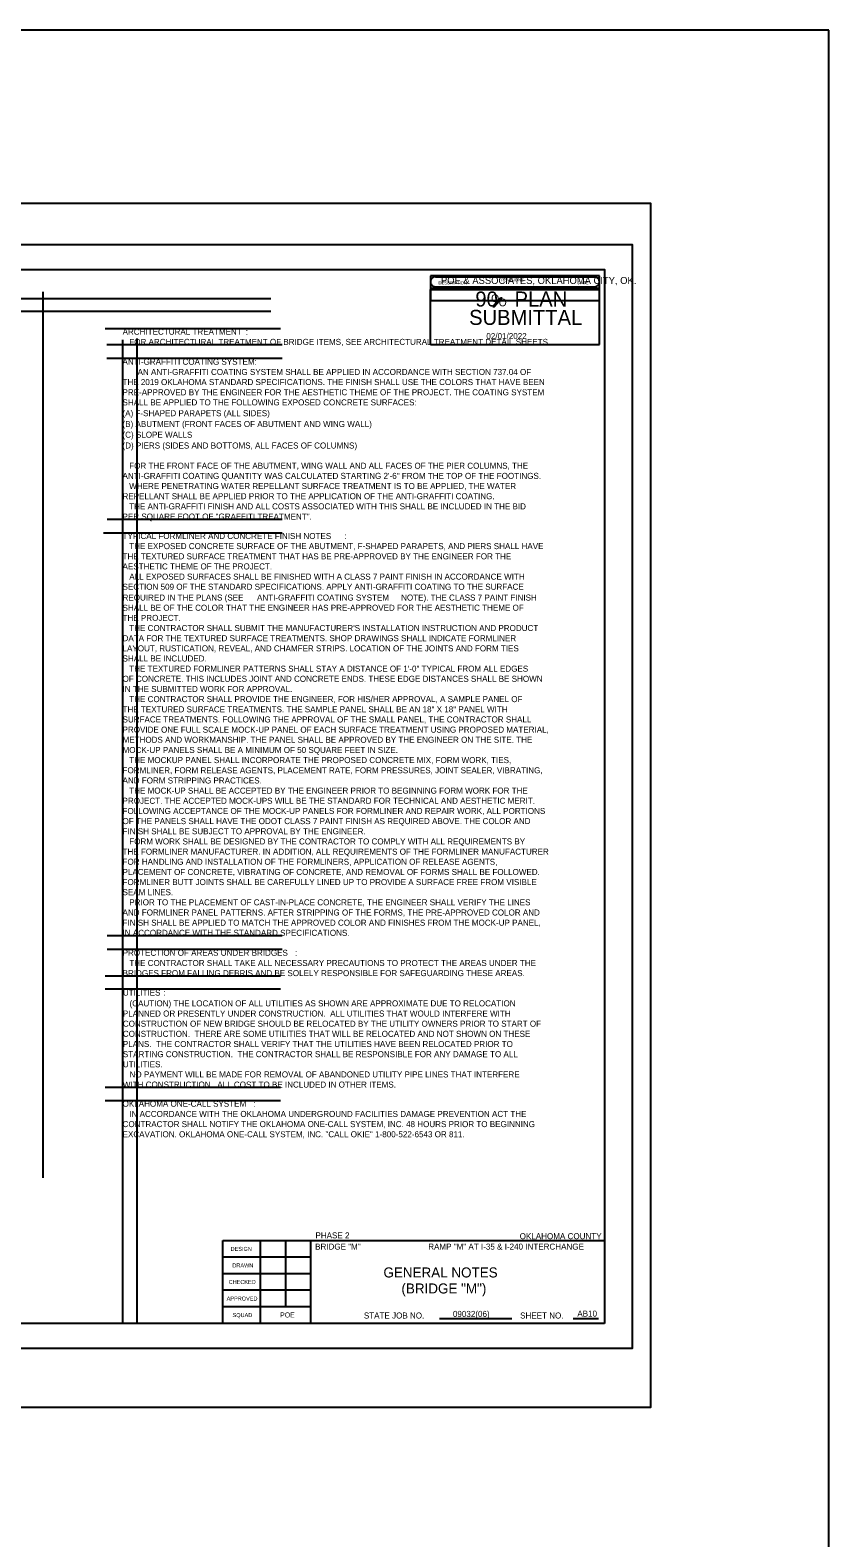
# Model space of a CAD drawing. Extents: x 12303.1 to 12355.9, y 579 to 640.5.
# Drawn here: x 12340.01 to 12355.91, y 610.44 to 640.49 of the extents above; entities that cross this region are included whole.
import ezdxf

# ---------------------------------------------------------------- set-up
doc = ezdxf.new("R2010")
doc.units = 0
for name, color, linetype in [('S', 7, 'Continuous'), ('SHT_Plot_Shape_Full', 7, 'Continuous'), ('SHT_Plot_Shape_Half', 7, 'Continuous'), ('SHT_Sheet_Border', 7, 'Continuous'), ('SHT_Stamp_90_Submit', 7, 'Continuous'), ('SHT_Stamp_Rev_Block', 7, 'Continuous'), ('SHT_Standard_Sheet_Lines', 7, 'Continuous'), ('SHT_Standard_Sheet_Txt', 7, 'Continuous'), ('T', 7, 'Continuous'), ('T-Title', 7, 'Continuous')]:
    doc.layers.add(name, color=color, linetype=linetype)

msp = doc.modelspace()

# ---------------------------------------------------------------- linework, layer by layer
at = {"layer": 'Defpoints'}
for p, q in [((12340.263, 635.276), (12340.263, 617.62)), ((12319.948, 635.141), (12344.799, 635.141)), ((12319.948, 634.891), (12344.799, 634.891)), ((12344.991, 634.538), (12341.502, 634.538)), ((12341.85, 634.316), (12341.85, 614.717)), ((12342.134, 634.344), (12342.134, 614.717)), ((12345.028, 634.215), (12341.539, 634.215)), ((12345.028, 633.945), (12341.539, 633.945)), ((12345.03, 630.735), (12341.54, 630.735)), ((12344.96, 630.466), (12341.471, 630.466)), ((12345.03, 630.466), (12341.54, 630.466)), ((12345.03, 622.44), (12341.54, 622.44)), ((12345.03, 622.17), (12341.54, 622.17)), ((12344.991, 621.637), (12341.502, 621.637)), ((12344.991, 621.375), (12341.502, 621.375)), ((12344.991, 619.416), (12341.502, 619.416)), ((12344.991, 619.154), (12341.502, 619.154))]:
    msp.add_line(p, q, dxfattribs=at)
at = {"layer": 'S'}
msp.add_lwpolyline([(12355.912, 640.488), (12312.476, 640.488), (12312.476, 579.031), (12355.912, 579.031)], close=True, dxfattribs=at)
at = {"layer": 'SHT_Plot_Shape_Full'}
msp.add_lwpolyline([(12316.36, 637.042), (12352.36, 637.042), (12352.36, 613.042), (12316.36, 613.042)], close=True, dxfattribs=at)
at = {"layer": 'SHT_Plot_Shape_Half'}
msp.add_lwpolyline([(12317.998, 636.217), (12351.998, 636.217), (12351.998, 614.217), (12317.998, 614.217)], close=True, dxfattribs=at)
at = {"layer": 'SHT_Sheet_Border'}
for p, q in [((12343.848, 614.717), (12343.848, 616.367)), ((12343.848, 616.367), (12351.448, 616.367)), ((12345.598, 614.717), (12345.598, 616.368))]:
    msp.add_line(p, q, dxfattribs=at)
msp.add_lwpolyline([(12351.448, 614.717), (12319.948, 614.717), (12319.948, 635.717), (12351.448, 635.717)], close=True, dxfattribs=at)
at = {"layer": 'SHT_Stamp_90_Submit'}
for p, q in [((12348.079, 635.572), (12351.245, 635.572)), ((12347.979, 635.322), (12351.345, 635.322)), ((12347.979, 634.223), (12347.979, 635.322)), ((12348.079, 635.372), (12351.245, 635.372)), ((12349.222, 634.984), (12349.377, 635.157)), ((12349.24, 634.984), (12349.395, 635.157)), ((12349.245, 634.984), (12349.4, 635.157)), ((12349.252, 634.984), (12349.408, 635.157)), ((12349.377, 635.157), (12349.408, 635.157)), ((12351.345, 634.223), (12351.345, 635.322)), ((12349.222, 634.984), (12349.252, 634.984)), ((12347.979, 634.223), (12351.345, 634.223))]:
    msp.add_line(p, q, dxfattribs=at)
for centre, start, end in [((12348.079, 635.473), 89.9952, 270), ((12351.245, 635.473), 270, 90.0048)]:
    msp.add_arc(centre, 0.1, start, end, dxfattribs=at)
at = {"layer": 'SHT_Stamp_Rev_Block'}
for p, q in [((12347.979, 635.593), (12347.979, 635.093)), ((12351.345, 635.593), (12347.979, 635.593)), ((12351.345, 635.093), (12351.345, 635.593)), ((12351.345, 635.343), (12347.979, 635.343)), ((12351.345, 635.093), (12347.979, 635.093))]:
    msp.add_line(p, q, dxfattribs=at)
at = {"layer": 'SHT_Standard_Sheet_Lines'}
for p, q in [((12344.598, 614.717), (12344.598, 616.368)), ((12345.098, 615.048), (12345.098, 616.368)), ((12348.159, 614.814), (12349.599, 614.814)), ((12350.823, 614.814), (12351.326, 614.814))]:
    msp.add_line(p, q, dxfattribs=at)
for points in [[(12345.598, 616.037), (12343.848, 616.037)], [(12345.598, 615.707), (12343.848, 615.707)], [(12345.598, 615.377), (12343.848, 615.377)], [(12345.598, 615.047), (12343.848, 615.047)]]:
    msp.add_lwpolyline(points, dxfattribs=at)

# ---------------------------------------------------------------- texts
at = {"layer": 'SHT_Stamp_90_Submit'}
for s, height, p in [('POE & ASSOCIATES, OKLAHOMA CITY, OK.', 0.14, (12348.189, 635.43)), ('90   PLAN', 0.3, (12348.874, 634.98)), ('O', 0.153, (12349.187, 635.069)), ('SUBMITTAL', 0.3, (12348.75, 634.614)), ('O', 0.153, (12349.339, 634.985)), ('02/01/2022', 0.12, (12349.093, 634.332))]:
    msp.add_text(s, height=height, rotation=360, dxfattribs=at).set_placement(p)
at = {"layer": 'SHT_Stamp_Rev_Block'}
for s, p in [('DESCRIPTION', (12348.139, 635.422)), ('REVISIONS', (12349.388, 635.481)), ('DATE', (12350.908, 635.426))]:
    msp.add_text(s, height=0.06, dxfattribs=at).set_placement(p)
at = {"layer": 'SHT_Standard_Sheet_Txt'}
for s, height, p in [('DESIGN', 0.08, (12344, 616.162)), ('DRAWN', 0.08, (12344.035, 615.832)), ('CHECKED', 0.08, (12343.961, 615.502)), ('APPROVED', 0.08, (12343.922, 615.172)), ('SQUAD', 0.08, (12344.039, 614.842)), ('STATE JOB NO.', 0.12, (12346.654, 614.814)), ('SHEET NO. ', 0.12, (12349.765, 614.814))]:
    msp.add_text(s, height=height, dxfattribs=at).set_placement(p)
at = {"layer": 'T'}
for s, height, p in [('ARCHITECTURAL TREATMENT', 0.12, (12341.85, 634.418)), ('   FOR ARCHITECTURAL TREATMENT OF BRIDGE ITEMS, SEE ARCHITECTURAL TREATMENT DETAIL SHEETS.', 0.12, (12341.85, 634.216)), (':', 0.12, (12344.302, 634.418)), ('ANTI-GRAFFITI COATING SYSTEM:', 0.12, (12341.848, 633.82)), ('AN ANTI-GRAFFITI COATING SYSTEM SHALL BE APPLIED IN ACCORDANCE WITH SECTION 737.04 OF ', 0.12, (12342.148, 633.617)), ('THE 2019 OKLAHOMA STANDARD SPECIFICATIONS. THE FINISH SHALL USE THE COLORS THAT HAVE BEEN ', 0.12, (12341.848, 633.415)), ('SHALL BE APPLIED TO THE FOLLOWING EXPOSED CONCRETE SURFACES:', 0.12, (12341.848, 633.01)), ('PRE-APPROVED BY THE ENGINEER FOR THE AESTHETIC THEME OF THE PROJECT. THE COATING SYSTEM ', 0.12, (12341.848, 633.212)), ('(A) F-SHAPED PARAPETS (ALL SIDES)', 0.12, (12341.848, 632.795)), ('(B) ABUTMENT (FRONT FACES OF ABUTMENT AND WING WALL)', 0.12, (12341.848, 632.58)), ('(C) SLOPE WALLS', 0.12, (12341.848, 632.366)), ('(D) PIERS (SIDES AND BOTTOMS, ALL FACES OF COLUMNS)', 0.12, (12341.848, 632.151)), ('   FOR THE FRONT FACE OF THE ABUTMENT, WING WALL AND ALL FACES OF THE PIER COLUMNS, THE ', 0.12, (12341.848, 631.748)), ('ANTI-GRAFFITI COATING QUANTITY WAS CALCULATED STARTING 2\'-6" FROM THE TOP OF THE FOOTINGS.', 0.12, (12341.848, 631.546)), ('REPELLANT SHALL BE APPLIED PRIOR TO THE APPLICATION OF THE ANTI-GRAFFITI COATING.', 0.12, (12341.848, 631.141)), ('   WHERE PENETRATING WATER REPELLANT SURFACE TREATMENT IS TO BE APPLIED, THE WATER ', 0.12, (12341.848, 631.343)), ('   THE ANTI-GRAFFITI FINISH AND ALL COSTS ASSOCIATED WITH THIS SHALL BE INCLUDED IN THE BID ', 0.12, (12341.848, 630.938)), ('PER SQUARE FOOT OF "GRAFFITI TREATMENT".', 0.12, (12341.848, 630.735)), ('TYPICAL FORMLINER AND CONCRETE FINISH NOTES', 0.12, (12341.849, 630.348)), (':', 0.12, (12346.267, 630.348)), ('THE TEXTURED SURFACE TREATMENT THAT HAS BE PRE-APPROVED BY THE ENGINEER FOR THE ', 0.12, (12341.849, 629.943)), ('   THE EXPOSED CONCRETE SURFACE OF THE ABUTMENT, F-SHAPED PARAPETS, AND PIERS SHALL HAVE ', 0.12, (12341.849, 630.146)), ('AESTHETIC THEME OF THE PROJECT.', 0.12, (12341.849, 629.741)), ('SECTION 509 OF THE STANDARD SPECIFICATIONS. APPLY ANTI-GRAFFITI COATING TO THE SURFACE ', 0.12, (12341.849, 629.336)), ('   ALL EXPOSED SURFACES SHALL BE FINISHED WITH A CLASS 7 PAINT FINISH IN ACCORDANCE WITH ', 0.12, (12341.849, 629.538)), ('REQUIRED IN THE PLANS (SEE ', 0.12, (12341.849, 629.121)), ('ANTI-GRAFFITI COATING SYSTEM', 0.12, (12344.526, 629.121)), (' NOTE). THE CLASS 7 PAINT FINISH ', 0.12, (12347.351, 629.121)), ('THE PROJECT.', 0.12, (12341.849, 628.716)), ('SHALL BE OF THE COLOR THAT THE ENGINEER HAS PRE-APPROVED FOR THE AESTHETIC THEME OF ', 0.12, (12341.849, 628.918)), ("   THE CONTRACTOR SHALL SUBMIT THE MANUFACTURER'S INSTALLATION INSTRUCTION AND PRODUCT ", 0.12, (12341.849, 628.513)), ('DATA FOR THE TEXTURED SURFACE TREATMENTS. SHOP DRAWINGS SHALL INDICATE FORMLINER ', 0.12, (12341.849, 628.311)), ('SHALL BE INCLUDED.', 0.12, (12341.849, 627.907)), ('LAYOUT, RUSTICATION, REVEAL, AND CHAMFER STRIPS. LOCATION OF THE JOINTS AND FORM TIES ', 0.12, (12341.849, 628.108)), ('   THE TEXTURED FORMLINER PATTERNS SHALL STAY A DISTANCE OF 1\'-0" TYPICAL FROM ALL EDGES ', 0.12, (12341.849, 627.704)), ('OF CONCRETE. THIS INCLUDES JOINT AND CONCRETE ENDS. THESE EDGE DISTANCES SHALL BE SHOWN ', 0.12, (12341.849, 627.502)), ('IN THE SUBMITTED WORK FOR APPROVAL.', 0.12, (12341.849, 627.299)), ('   THE CONTRACTOR SHALL PROVIDE THE ENGINEER, FOR HIS/HER APPROVAL, A SAMPLE PANEL OF ', 0.12, (12341.849, 627.097)), ('THE TEXTURED SURFACE TREATMENTS. THE SAMPLE PANEL SHALL BE AN 18" X 18" PANEL WITH ', 0.12, (12341.849, 626.894)), ('SURFACE TREATMENTS. FOLLOWING THE APPROVAL OF THE SMALL PANEL, THE CONTRACTOR SHALL ', 0.12, (12341.849, 626.692)), ('PROVIDE ONE FULL SCALE MOCK-UP PANEL OF EACH SURFACE TREATMENT USING PROPOSED MATERIAL, ', 0.12, (12341.849, 626.489)), ('METHODS AND WORKMANSHIP. THE PANEL SHALL BE APPROVED BY THE ENGINEER ON THE SITE. THE ', 0.12, (12341.849, 626.287)), ('MOCK-UP PANELS SHALL BE A MINIMUM OF 50 SQUARE FEET IN SIZE.', 0.12, (12341.849, 626.084)), ('   THE MOCKUP PANEL SHALL INCORPORATE THE PROPOSED CONCRETE MIX, FORM WORK, TIES, ', 0.12, (12341.849, 625.882)), ('AND FORM STRIPPING PRACTICES.', 0.12, (12341.849, 625.476)), ('FORMLINER, FORM RELEASE AGENTS, PLACEMENT RATE, FORM PRESSURES, JOINT SEALER, VIBRATING, ', 0.12, (12341.849, 625.679)), ('   THE MOCK-UP SHALL BE ACCEPTED BY THE ENGINEER PRIOR TO BEGINNING FORM WORK FOR THE ', 0.12, (12341.849, 625.274)), ('PROJECT. THE ACCEPTED MOCK-UPS WILL BE THE STANDARD FOR TECHNICAL AND AESTHETIC MERIT. ', 0.12, (12341.849, 625.071)), ('FOLLOWING ACCEPTANCE OF THE MOCK-UP PANELS FOR FORMLINER AND REPAIR WORK, ALL PORTIONS ', 0.12, (12341.849, 624.869)), ('OF THE PANELS SHALL HAVE THE ODOT CLASS 7 PAINT FINISH AS REQUIRED ABOVE. THE COLOR AND ', 0.12, (12341.849, 624.666)), ('FINISH SHALL BE SUBJECT TO APPROVAL BY THE ENGINEER.', 0.12, (12341.849, 624.464)), ('   FORM WORK SHALL BE DESIGNED BY THE CONTRACTOR TO COMPLY WITH ALL REQUIREMENTS BY ', 0.12, (12341.849, 624.261)), ('THE FORMLINER MANUFACTURER. IN ADDITION, ALL REQUIREMENTS OF THE FORMLINER MANUFACTURER ', 0.12, (12341.849, 624.058)), ('FOR HANDLING AND INSTALLATION OF THE FORMLINERS, APPLICATION OF RELEASE AGENTS, ', 0.12, (12341.849, 623.856)), ('PLACEMENT OF CONCRETE, VIBRATING OF CONCRETE, AND REMOVAL OF FORMS SHALL BE FOLLOWED. ', 0.12, (12341.849, 623.653)), ('FORMLINER BUTT JOINTS SHALL BE CAREFULLY LINED UP TO PROVIDE A SURFACE FREE FROM VISIBLE ', 0.12, (12341.849, 623.451)), ('SEAM LINES.', 0.12, (12341.849, 623.25)), ('   PRIOR TO THE PLACEMENT OF CAST-IN-PLACE CONCRETE, THE ENGINEER SHALL VERIFY THE LINES ', 0.12, (12341.849, 623.048)), ('AND FORMLINER PANEL PATTERNS. AFTER STRIPPING OF THE FORMS, THE PRE-APPROVED COLOR AND ', 0.12, (12341.849, 622.845)), ('FINISH SHALL BE APPLIED TO MATCH THE APPROVED COLOR AND FINISHES FROM THE MOCK-UP PANEL, ', 0.12, (12341.849, 622.642)), ('IN ACCORDANCE WITH THE STANDARD SPECIFICATIONS.', 0.12, (12341.849, 622.44)), ('PROTECTION OF AREAS UNDER BRIDGES', 0.12, (12341.851, 622.042)), ('   THE CONTRACTOR SHALL TAKE ALL NECESSARY PRECAUTIONS TO PROTECT THE AREAS UNDER THE ', 0.12, (12341.851, 621.839)), (':', 0.12, (12345.284, 622.042)), ('BRIDGES FROM FALLING DEBRIS AND BE SOLELY RESPONSIBLE FOR SAFEGUARDING THESE AREAS.', 0.12, (12341.851, 621.637)), ('UTILITIES', 0.12, (12341.855, 621.249)), (':', 0.12, (12342.667, 621.249)), ('   (CAUTION) THE LOCATION OF ALL UTILITIES AS SHOWN ARE APPROXIMATE DUE TO RELOCATION ', 0.12, (12341.855, 621.034)), ('CONSTRUCTION OF NEW BRIDGE SHOULD BE RELOCATED BY THE UTILITY OWNERS PRIOR TO START OF ', 0.12, (12341.855, 620.629)), ('PLANNED OR PRESENTLY UNDER CONSTRUCTION.  ALL UTILITIES THAT WOULD INTERFERE WITH ', 0.12, (12341.855, 620.832)), ('CONSTRUCTION.  THERE ARE SOME UTILITIES THAT WILL BE RELOCATED AND NOT SHOWN ON THESE', 0.12, (12341.855, 620.427)), ('STARTING CONSTRUCTION.  THE CONTRACTOR SHALL BE RESPONSIBLE FOR ANY DAMAGE TO ALL ', 0.12, (12341.855, 620.022)), ('PLANS.  THE CONTRACTOR SHALL VERIFY THAT THE UTILITIES HAVE BEEN RELOCATED PRIOR TO ', 0.12, (12341.855, 620.224)), ('UTILITIES.', 0.12, (12341.855, 619.821)), ('WITH CONSTRUCTION.  ALL COST TO BE INCLUDED IN OTHER ITEMS. ', 0.12, (12341.855, 619.416)), ('   NO PAYMENT WILL BE MADE FOR REMOVAL OF ABANDONED UTILITY PIPE LINES THAT INTERFERE ', 0.12, (12341.855, 619.618)), ('OKLAHOMA ONE-CALL SYSTEM', 0.12, (12341.85, 619.034)), ('   IN ACCORDANCE WITH THE OKLAHOMA UNDERGROUND FACILITIES DAMAGE PREVENTION ACT THE ', 0.12, (12341.85, 618.831)), (':', 0.12, (12344.458, 619.034)), ('CONTRACTOR SHALL NOTIFY THE OKLAHOMA ONE-CALL SYSTEM, INC. 48 HOURS PRIOR TO BEGINNING ', 0.12, (12341.85, 618.628)), ('EXCAVATION. OKLAHOMA ONE-CALL SYSTEM, INC. "CALL OKIE" 1-800-522-6543 OR 811.', 0.12, (12341.85, 618.426)), ('PHASE 2', 0.12, (12345.69, 616.411)), ('OKLAHOMA COUNTY', 0.12, (12349.756, 616.395)), ('BRIDGE "M"', 0.12, (12345.683, 616.187)), ('RAMP "M" AT I-35 & I-240 INTERCHANGE', 0.12, (12347.935, 616.187)), ('POE', 0.1, (12344.987, 614.835)), ('09032(06)', 0.12, (12348.427, 614.846)), ('AB10', 0.12, (12350.904, 614.852))]:
    msp.add_text(s, height=height, dxfattribs=at).set_placement(p)
at = {"layer": 'T-Title'}
for s, p in [('GENERAL NOTES', (12347.044, 615.632)), ('(BRIDGE "M")', (12347.402, 615.313))]:
    msp.add_text(s, height=0.2, dxfattribs=at).set_placement(p)

doc.saveas('drawing.dxf')
